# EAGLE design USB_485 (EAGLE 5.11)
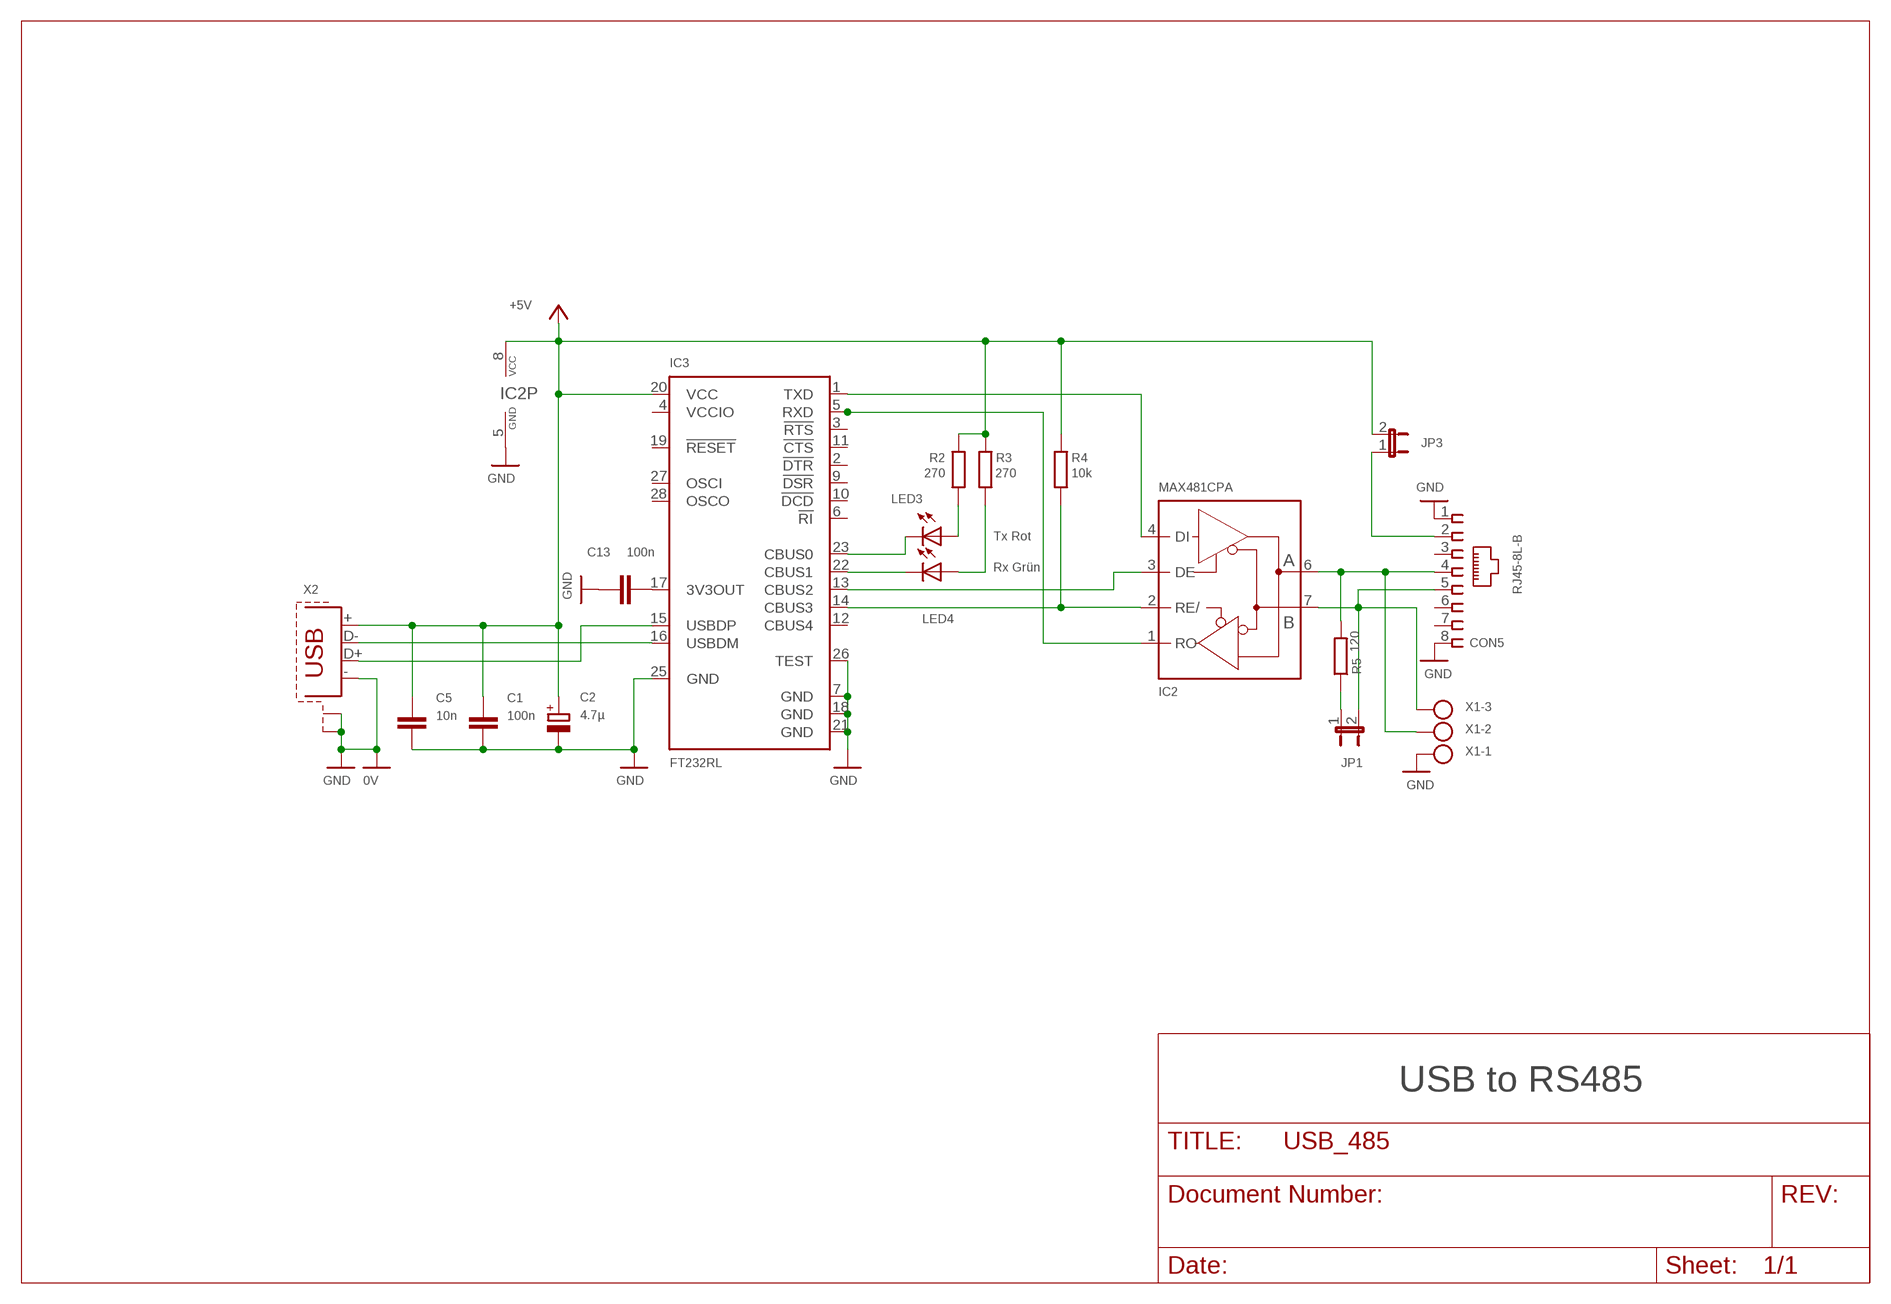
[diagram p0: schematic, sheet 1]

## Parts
C1  100n  C-EU025-025X050  [C025-025X050]
C2  4.7µ  CPOL-EUE2,5-6E  [E2,5-6E]
C5  10n  C-EU025-025X050  [C025-025X050]
C13  100n  C-EU025-025X050  [C025-025X050]
CON5  RJ45-8L-B  [RJ45-NO-SHIELD]
IC2  MAX481CPA  [DIL08]
IC3  FT232RL  [SSOP28]
JP1  JP1E  [JP1]
JP3  JP1E  [JP1]
LED3  Tx Rot  LED3MM  [LED3MM]
LED4  Rx Grün  LED3MM  [LED3MM]
R2  270  R-EU_0204/7  [0204/7@1]
R3  270  R-EU_0204/7  [0204/7@1]
R4  10k  R-EU_0204/7  [0204/7@1]
R5  120  R-EU_0204/7  [0204/7@1]
X1  W237-103  [W237-103]
X2  AWF  [AWF]

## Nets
+3.3V: C13.2 IC3.17(3V3OUT)
+5V: C1.2 C2.+ C5.2 IC2.8(VCC) IC3.20(VCC) JP3.2 R2.2 R3.2 R4.2 X2.+
A: CON5.4 IC2.6(A) R5.2 X1.2
B: CON5.5 IC2.7(B) JP1.2 X1.3
D+: IC3.15(USBDP) X2.D+
D-: IC3.16(USBDM) X2.D-
GND: C1.1 C2.- C5.1 C13.1 CON5.1 CON5.8 IC2.5(GND) IC3.7(GND) IC3.18(GND) IC3.21(GND) IC3.25(GND) IC3.26(TEST) X1.1 X2.- X2.SHIELD1(S1) X2.SHIELD2(S2) ; supply symbol labelled 0V
N$1: IC3.22(CBUS1) LED4.K(C)
N$2: IC2.1(RO) IC3.5(RXD)
N$3: JP1.1 R5.1
N$4: IC2.2(RE/) IC3.14(CBUS3) R4.1
N$5: LED3.A R2.1
N$6: LED4.A R3.1
N$7: IC2.3(DE) IC3.13(CBUS2)
N$8: IC2.4(DI) IC3.1(TXD)
N$9: IC3.23(CBUS0) LED3.K(C)
N$10: CON5.2 JP3.1
Unconnected: CON5.3 CON5.6 CON5.7 IC3.2(!DTR) IC3.3(!RTS) IC3.6(!RI) IC3.9(!DSR) IC3.10(!DCD) IC3.11(!CTS) IC3.12(CBUS4) IC3.19(!RESET) IC3.27(OSCI) IC3.28(OSCO)

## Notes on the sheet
- USB to RS485

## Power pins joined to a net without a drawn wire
VCCIO: IC3.4(VCCIO)

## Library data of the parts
C1 C5 C13 = rcl:C-EU: CAPACITOR, European symbol
C2 = rcl:CPOL-EU: POLARIZED CAPACITOR, European symbol
CON5 = con-tycoelectronics:RJ45: CORCOM Modular RJ Jacks No Shield Source: www.tycoelectronics.com .. ENG_DS_1654001_1099_RJ_L_0507.pdf
IC2 = maxim:MAX481CPA: RS485 TRANSEIVER
IC3 = ftdichip:FT232R: Source: http://www.ftdichip.com/Documents/DataSheets/DS_FT232R_v104.pdf
JP1 JP3 = jumper:JP1E: JUMPER
LED3 LED4 = led:LED: LED
R2-R5 = rcl:R-EU_: RESISTOR, European symbol
X1 = con-wago-500:W237-103: WAGO SCREW CLAMP; MPN: 237-103; OC_FARNELL: unknown; OC_NEWARK: 18M7116
X2 = con-berg:AWF

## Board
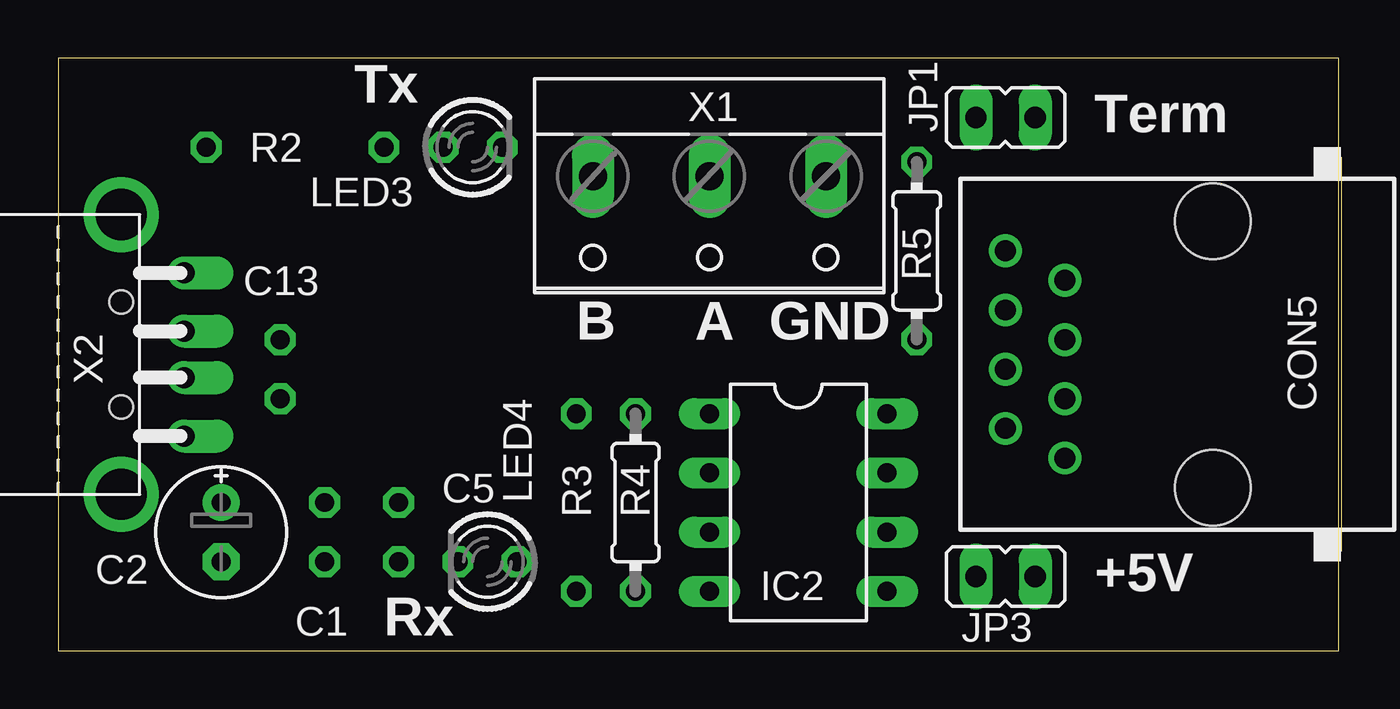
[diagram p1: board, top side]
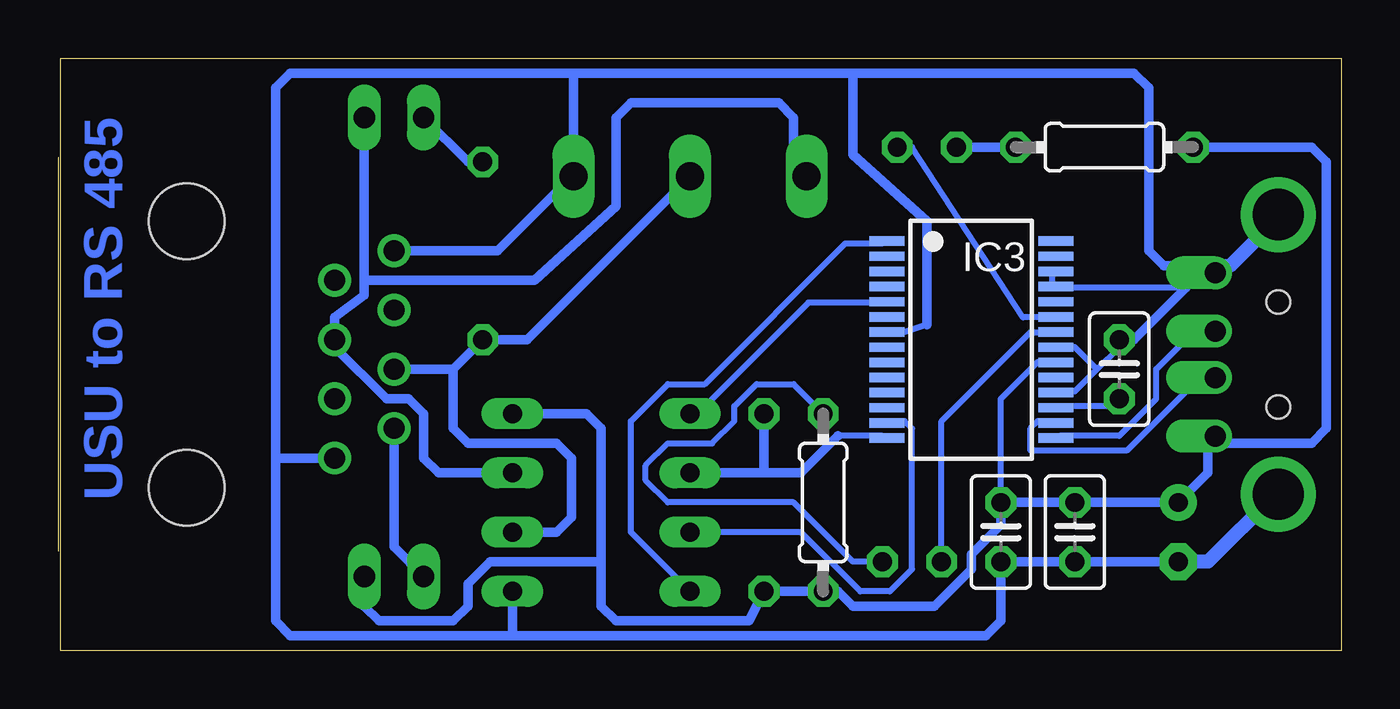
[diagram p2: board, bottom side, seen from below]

Size 55.04 x 25.4 mm. Coordinates in mm from the lower left corner, seen from the top.
Outline: 0,0 54.93,0 54.93,25.4 0,25.4 0,0
Copper layers (1*16): Top 0.035mm / dielectric 1.5mm / Bottom 0.035mm
Design rules "default": minimum track width 10mil, minimum drill 24mil, track to track 8mil, track to pad 8mil, pad to pad 8mil, via to via 8mil, smd to smd 8mil, copper to edge 40mil, drill to drill 8mil, minimum pad ring 10mil, minimum via ring 8mil, stop-mask expansion 4mil, vias tented up to drill 0mil, thermal gap 10mil

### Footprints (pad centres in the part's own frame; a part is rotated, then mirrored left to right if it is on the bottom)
C025-025X050 = drill 0.813 octagon: 1 -1.27,0; 2 1.27,0
E2,5-6E = drill 0.813 pad 1.575 round: + -1.27,0 | drill 0.813 pad 1.575 octagon: - 1.27,0
RJ45-NO-SHIELD = drill 0.9 pad 1.4 round: 1 -4.445,6.35; 2 -3.175,8.89; 3 -1.905,6.35; 4 -0.635,8.89; 5 0.635,6.35; 6 1.905,8.89; 7 3.175,6.35; 8 4.445,8.89 | hole 3.251: -5.715,0; 5.715,0
DIL08 = drill 0.813 long: 1 -3.81,-3.81; 2 -1.27,-3.81; 3 1.27,-3.81; 4 3.81,-3.81; 5 3.81,3.81; 6 1.27,3.81; 7 -1.27,3.81; 8 -3.81,3.81
SSOP28 = smd 0.4 x 1.5: 1 -4.225,-3.625; 2 -3.575,-3.625; 3 -2.925,-3.625; 4 -2.275,-3.625; 5 -1.625,-3.625; 6 -0.975,-3.625; 7 -0.325,-3.625; 8 0.325,-3.625; 9 0.975,-3.625; 10 1.625,-3.625; 11 2.275,-3.625; 12 2.925,-3.625; 13 3.575,-3.625; 14 4.225,-3.625; 15 4.225,3.625; 16 3.575,3.625; 17 2.925,3.625; 18 2.275,3.625; 19 1.625,3.625; 20 0.975,3.625; 21 0.325,3.625; 22 -0.325,3.625; 23 -0.975,3.625; 24 -1.625,3.625; 25 -2.275,3.625; 26 -2.925,3.625; 27 -3.575,3.625; 28 -4.225,3.625
JP1 = drill 0.914 long: 1 0,-1.27; 2 0,1.27
LED3MM = drill 0.813 octagon: A -1.27,0; K 1.27,0
0204/7@1 = drill 0.813 octagon: 1 -3.81,0; 2 3.81,0
W237-103 = drill 1.194 long: 1 -5,-1.29; 2 0,-1.29; 3 5,-1.29
AWF = drill 0.9 offset: + 5.4,-3.5; - 5.4,3.5; D+ 5.4,1; D- 5.4,-1 | drill 2.2 round: SHIELD1 2.7,6; SHIELD2 2.7,-6 | hole 1: 2.7,2.25; 2.7,-2.25

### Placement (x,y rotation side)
C1  11.43,5.08 90 bottom
C2  6.99,5.08 270 top
C5  14.61,5.08 90 bottom
C13  9.53,12.06 270 bottom
CON5  49.53,12.7 90 top
IC2  31.75,6.35 270 top
IC3  15.88,13.34 270 bottom
JP1  40.64,22.86 270 top
JP3  40.64,3.17 270 top
LED3  17.78,21.59 0 top
LED4  18.41,3.81 180 top
R2  10.16,21.59 0 bottom
R3  22.23,6.35 270 bottom
R4  24.77,6.35 270 top
R5  36.83,17.14 270 top
X1  27.94,19.05 180 top
X2  0,12.7 0 top

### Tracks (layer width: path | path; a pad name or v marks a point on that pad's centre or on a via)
+3.3V
  Bottom 0.254: C13.2 9.84,10.48 12.06,10.48 IC3.17
+5V
  Bottom 0.254: C5.2 14.61,10.79 13.02,12.38 12.38,12.38 IC3.20 12.06,12.38
  Bottom 0.406: 5.71,8.89 5.71,7.62 C2.+ C1.2 C5.2 14.61,5.4 15.88,4.13 15.88,3.49 17.46,1.91 20.95,1.91 21.59,2.54 R3.2 R4.2 25.4,1.27 31.11,1.27 31.75,1.91 31.75,3.81 | 31.75,3.81 31.75,9.53 32.38,10.16 IC2.8 | 31.75,3.81 36.51,3.81 37.47,2.86 37.47,1.91 38.1,1.27 41.27,1.27 41.91,1.91 JP3.2 | 5.71,8.89 1.27,8.89 0.64,9.53 0.64,20.95 1.27,21.59 R2.2 | 5.71,8.89 X2.+
A
  Bottom 0.254: 27.94,20.32 X1.2
  Bottom 0.406: 38.1,12.06 R5.2 34.92,13.34 27.94,20.32 | 38.1,12.06 CON5.4 | IC2.6 33.66,5.08 33.02,5.71 33.02,8.26 33.66,8.89 37.47,8.89 38.1,9.53 38.1,12.06
B
  Bottom 0.305: CON5.5 43.18,13.02
  Bottom 0.406: CON5.5 43.18,14.29 41.91,15.24 41.91,15.88 | IC2.7 38.73,7.62 39.37,8.26 39.37,10.16 40.01,10.79 40.96,10.79 43.18,13.02 | 41.91,15.88 34.61,15.88 31.11,19.05 31.11,22.86 30.48,23.5 24.13,23.5 23.5,22.86 23.5,20.89 X1.3 | 41.91,15.88 JP1.2
D+
  Bottom 0.254: IC3.15 12.06,9.21 9.53,9.21 7.94,10.79 7.94,12.06 6.35,13.65 5.71,13.65 X2.D+
D-
  Bottom 0.254: IC3.16 12.38,9.84 13.02,9.84 13.34,9.53 13.34,8.57 9.21,8.57 6.35,11.43 5.71,11.43 X2.D-
GND
  Bottom 0.254: IC3.21 12.06,13.02 11.43,13.02 10.48,12.06 | 17.78,13.97 18.73,13.65 19.37,13.65 IC3.7 | 12.06,16.19 IC3.26 12.38,16.19 12.38,15.56 IC3.25 12.06,15.56 6.67,15.56 | X1.1 33.02,20.32 | 10.48,12.06 9.53,13.02 C13.1 | 10.48,12.06 11.43,11.11 12.06,11.11 IC3.18 | 6.99,16.51 7.3,16.51 | 5.71,16.51 X2.-
  Bottom 0.406: C2.- C1.1 C5.1 14.61,1.27 15.24,0.64 35.56,0.64 | 17.78,13.97 17.78,18.41 20.95,21.27 20.95,24.77 | CON5.8 36.2,17.14 33.02,20.32 | 35.56,0.64 IC2.5 | 45.72,8.26 45.72,1.27 45.09,0.64 35.56,0.64 | C13.1 8.89,13.34 6.67,15.56 5.71,16.51 6.99,16.51 7.62,16.51 8.26,17.14 8.26,24.13 8.89,24.77 20.95,24.77 | 45.72,8.26 CON5.1 | 45.72,8.26 45.72,24.13 45.09,24.77 33.02,24.77 | X2.SHIELD2 2.86,6.67 | 33.02,24.77 20.95,24.77 | X1.1 32.94,24.68 33.02,24.77
  Bottom 0.61: C2.- 5.71,3.81 2.86,6.67 | X2.SHIELD1 2.86,18.41 4.76,16.51 5.4,16.51 X2.-
N$1
  Bottom 0.254: LED4.K 17.14,9.84 13.34,13.65 12.38,13.65 IC3.22
N$2
  Bottom 0.254: IC2.1 27.62,10.16 22.86,14.92 19.68,14.92 IC3.5
N$3
  Bottom 0.406: R5.1 37.47,20.95 JP1.1
N$4
  Bottom 0.254: 21.59,9.21 19.68,9.21 IC3.14
  Bottom 0.406: 21.59,9.21 23.18,7.62 24.77,7.62 | 24.77,7.62 IC2.2 | 24.77,7.62 R4.1
N$5
  Bottom 0.406: R2.1 LED3.A
N$6
  Bottom 0.254: LED4.A 20.95,3.81 23.5,6.35 28.89,6.35 29.84,7.3 29.84,7.94 28.89,8.89 26.99,8.89 26.04,9.84 26.04,10.48 25.08,11.43 23.5,11.43 R3.1
N$7
  Bottom 0.254: IC2.3 23.18,5.08 20.64,2.54 19.37,2.54 18.41,3.49 18.41,9.53 18.73,9.84 19.37,9.84 IC3.13
N$8
  Bottom 0.254: IC2.4 30.48,5.08 30.48,9.84 28.89,11.43 27.3,11.43 21.27,17.46 19.68,17.46 IC3.1
N$9
  Bottom 0.254: LED3.K 18.41,21.59 13.65,14.29 12.38,14.29 IC3.23
N$10
  Bottom 0.406: CON5.2 40.64,4.45 JP3.1

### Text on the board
Bottom: USU to RS 485
tNames: Tx | Term | B | A | GND | +5V | Rx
